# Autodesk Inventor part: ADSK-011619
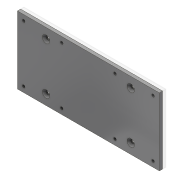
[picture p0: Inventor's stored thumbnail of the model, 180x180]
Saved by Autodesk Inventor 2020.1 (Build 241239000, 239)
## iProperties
Created: 2000-02
Part Number: ADSK-011619
Document SubType Name: Modeling
Description: PLT-XX,FH,XX,05,200,100,(4)Z,(8)E,MOUNT,CONEDRIVE,mho30
Designer: glanglot
Material: Pearson HRS
Density: 7.83 g/cm^3
Appearance: Steel
Mass: 12559 g
Surface Area: 2918.6 cm^2
Volume: 1603.96 cm^3
Control State: 0
Checked Out: False
Master: False
Shininess: 25.0
Length Units: 11269
Angle Units: 11279
Time Units: 11290
Mass Units: 11283
Length Display Precision: 5
Angle Display Precision: 2
Compacted: True
Cutlength: 20
Material Desc: FLAT,HRS,0.500X10.000
Material_Number: A084310
Dimensions: 533x254x12 mm
Mass: 12,559 kg
DocNumber: ADSK-011619.ipt
Folder: 01 - Themengebiete\Simplification\01 - Packaging machine\
VDS_Category: 3D Komponenten
Density: 7.83
Volumn: 1710.7838768124984
Area: 2890.921637499998
PropertySet Name: Model Information
Author: glanglot
Revision Number: -
Title: PLT-XX,FH,XX,05,200,100,(4)Z,(8)E,MOUNT,CONEDRIVE,mho30
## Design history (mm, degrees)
sketch "Sketch1"
  geometry: L1 (-266.5, 127)-(266.5, 127); L2 (266.5, 127)-(266.5, -127); L3 (266.5, -127)-(-266.5, -127); L4 (-266.5, -127)-(-266.5, 127); L5 (-243, -106.5)-(-100, -106.5); L6 (-100, -106.5)-(-100, 106.5); L7 (-100, 106.5)-(-243, 106.5); L8 (-243, 106.5)-(-243, -106.5); L9 (100, -106.5)-(243, -106.5); L10 (243, -106.5)-(243, 106.5); L11 (243, 106.5)-(100, 106.5); L12 (100, 106.5)-(100, -106.5); L13 (-100, 0)-(100, 0); 9 further points
  constraints: 26 end point, 6 parallel, 5 coincident, 5 midpoint, 3 horizontal, 3 perpendicular, 2 collinear, 2 horizontal alignment, 2 vertical alignment
  dimensions: "d44" = 143 distance of L5.start L5.end; "d45" = 143 distance of L9.start L9.end (= d44); "d46" = 213 distance of L7.end L5.start; "d47" = 200 distance of L13.start L13.end; "d48" = 533 distance of L1.start L1.end; "d49" = 254 distance of L1.end L2.end
node "Extrusion1" dims "d26" = 12, "d27" = 0
node "Hole1" dims "d28" = 10.106, "d29" = 25.4, "d30" = 6.35, "d31" = 82 deg, "d32" = 32.3, "d33" = 118 deg, "d50" = 24
node "Hole2" dims "d38" = 13.5, "d39" = 28, "d40" = 6.35, "d41" = 90 deg, "d42" = 19.05, "d43" = 118 deg, "d51" = 6
  sketch "Sketch2"
    geometry: L1 (-266.5, -127)-(266.5, -127) reference; L2 (-243, 106.5)-(-100, 106.5); L3 (-100, -106.5)-(-243, -106.5); L4 (100, -106.5)-(243, -106.5); L5 (243, 106.5)-(100, 106.5); L6 (159, -89)-(-159, -89); L7 (-159, -89)-(-159, 89); L8 (-159, 89)-(159, 89); L9 (159, 89)-(159, -89); L10 (266.5, -127)-(266.5, 127) reference; C1 r 5.053 at (-243, 106.5) reference; C2 r 5.053 at (-100, 106.5) reference; C3 r 5.053 at (-100, -106.5) reference; C4 r 5.053 at (-243, -106.5) reference; C5 r 5.053 at (100, 106.5) reference; C6 r 5.053 at (243, 106.5) reference; C7 r 5.053 at (243, -106.5) reference; C8 r 5.053 at (100, -106.5) reference; 6 further points
    constraints: 16 end point, 4 midpoint, 2 coincident, 2 parallel, 1 horizontal, 1 horizontal alignment, 1 perpendicular, 1 vertical alignment
    dimensions: "d52" = 318 distance of L6.start L6.end; "d53" = 178 distance of L6.end L7.end
node "Solide1"
node "Corps solides"
node "Corps surfaciques"
